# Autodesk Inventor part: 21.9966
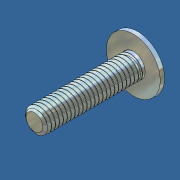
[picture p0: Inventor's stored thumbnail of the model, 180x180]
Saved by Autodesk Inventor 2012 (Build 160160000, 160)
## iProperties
Created: 2009-08
Part Number: 21.9966
Document SubType Name: Modeling
Designer: Administrator
Density: 7.85 g/cm^3
Material: Steel
Description: M6x25 Button Head Flange Screw
Mass: 6.39724 g
Surface Area: 11.1522 cm^2
Volume: 0.814935 cm^3
Vendor: S
Title: M6x25 Button Head Flange Screw
Author: Administrator
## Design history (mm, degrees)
feature "Base1"
body "Solid1"
